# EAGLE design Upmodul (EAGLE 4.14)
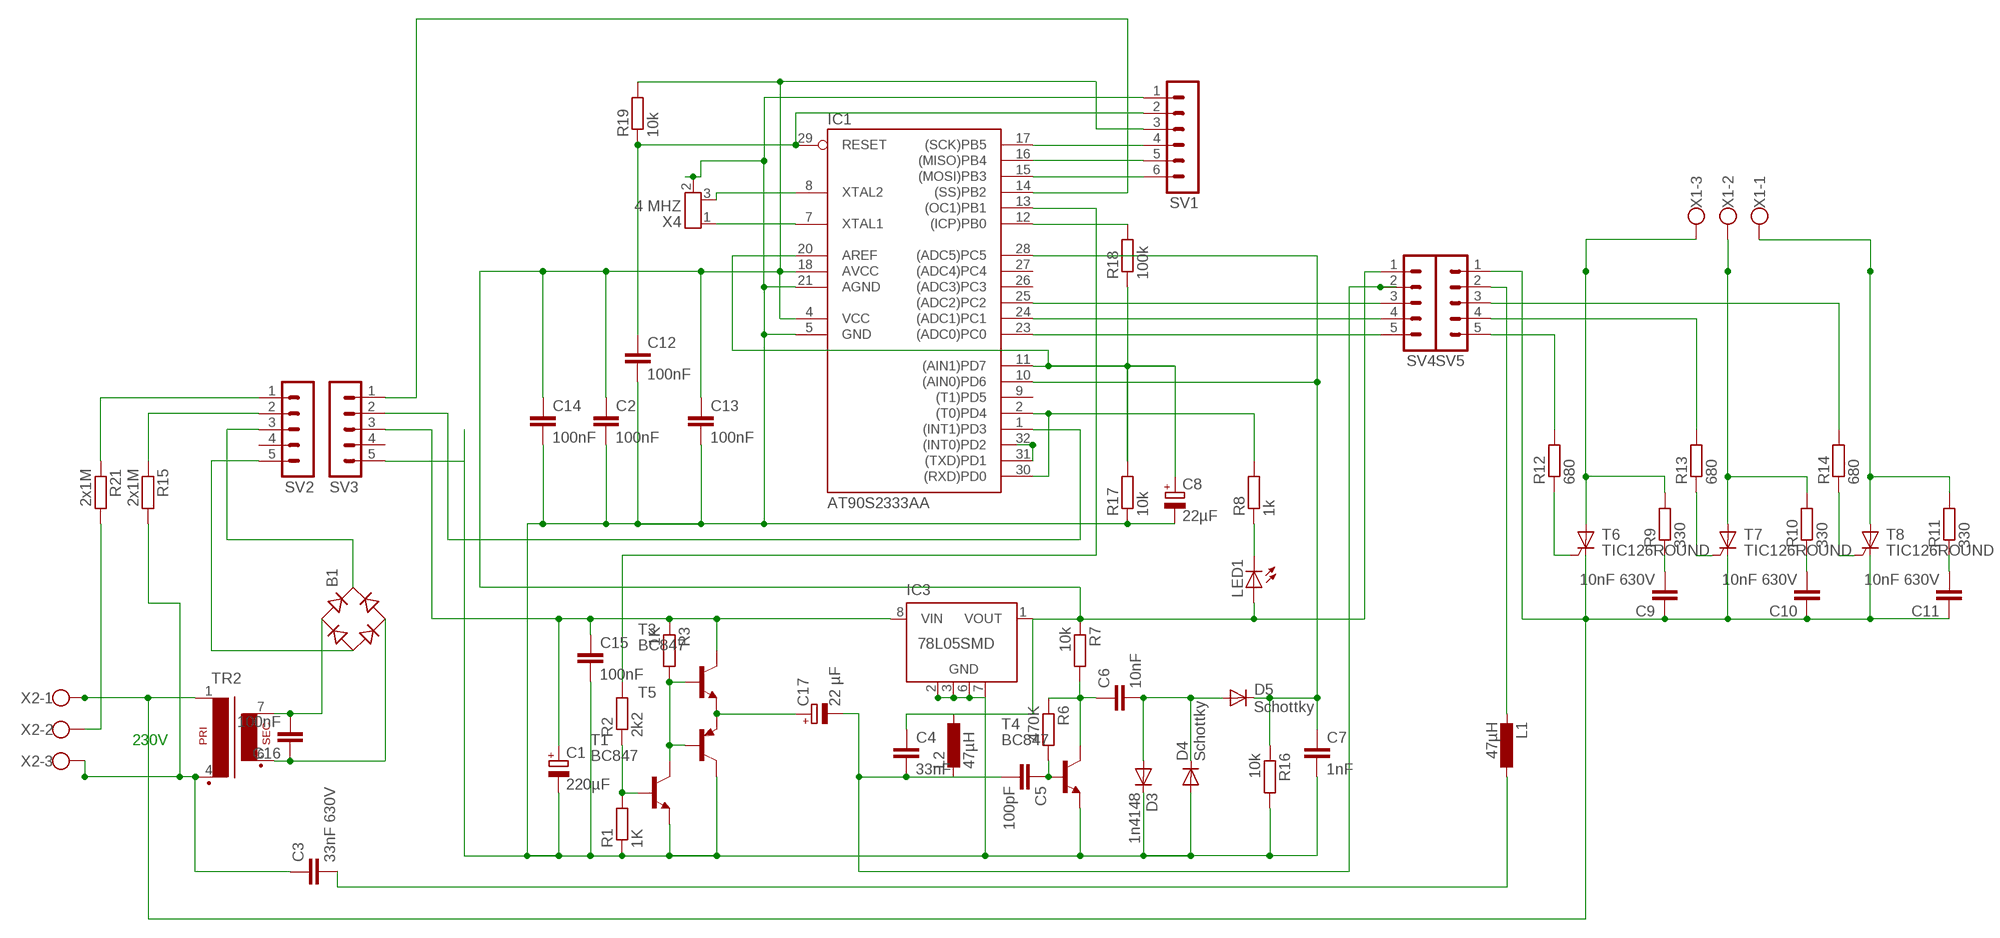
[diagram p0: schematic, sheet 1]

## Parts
B1  B-DIL  [B-DIL]
C1  220µF  CPOL-EUE5-10.5  [E5-10,5]
C2  100nF  C-EUC0805  [C0805]
C3  33nF 630V  C-EU075-032X103  [C075-032X103]
C4  33nF  C-EUC0805  [C0805]
C5  100pF  C-EUC0805  [C0805]
C6  10nF  C-EUC0805  [C0805]
C7  1nF  C-EUC0805  [C0805]
C8  22µF  CPOL-EUE2.5-5  [E2,5-5]
C9  10nF 630V  C-EU075-032X103  [C075-032X103]
C10  10nF 630V  C-EU075-032X103  [C075-032X103]
C11  10nF 630V  C-EU075-032X103  [C075-032X103]
C12  100nF  C-EUC0805  [C0805]
C13  100nF  C-EUC0805  [C0805]
C14  100nF  C-EUC0805  [C0805]
C15  100nF  C-EUC0805  [C0805]
C16  100nF  C-EUC0805  [C0805]
C17  22 µF  CPOL-EUE5-8.5  [E5-8,5]
D3  1n4148  DIODE-DO214AA  [DO214AA]
D4  Schottky  DIODE-DO214AA  [DO214AA]
D5  Schottky  DIODE-DO214AA  [DO214AA]
IC1  AT90S2333AA  [TQFP32-08]
IC3  78L05SMD  [SO08]
L1  47µH  L-EU0207/2V  [0207/2V]
L2  47µH  L-EU0207/2V  [0207/2V]
LED1  LED3MM  [LED3MM]
R1  1K  R-EU_R0805  [R0805]
R2  2k2  R-EU_R0805  [R0805]
R3  1K  R-EU_M0805  [M0805]
R6  470K  R-EU_R0805  [R0805]
R7  10k  R-EU_M0805  [M0805]
R8  1k  R-EU_R0805  [R0805]
R9  330  R-EU_0207/2V  [0207/2V]
R10  330  R-EU_0207/2V  [0207/2V]
R11  330  R-EU_0207/2V  [0207/2V]
R12  680  R-EU_R0805  [R0805]
R13  680  R-EU_R0805  [R0805]
R14  680  R-EU_R0805  [R0805]
R15  2x1M  R-EU_0207/7  [0207/7]
R16  10k  R-EU_M0805  [M0805]
R17  10k  R-EU_R0805  [R0805]
R18  100k  R-EU_R0805  [R0805]
R19  10k  R-EU_R0805  [R0805]
R21  2x1M  R-EU_0207/2V  [0207/2V]
SV1  MA06-1  [MA06-1]
SV2  MA05-1  [MA05-1]
SV3  MA05-1  [MA05-1]
SV4  MA05-1  [MA05-1]
SV5  MA05-1  [MA05-1]
T1  BC847  [SOT23]
T3  BC847  [SOT23]
T4  BC847  [SOT23]
T5  BC857C-PNP-SOT23-BEC  [SOT23-BEC]
T6  TIC126ROUND  [TO220CS-ROUND]
T7  TIC126ROUND  [TO220CS-ROUND]
T8  TIC126ROUND  [TO220CS-ROUND]
TR2  EE20-1ALTERNATIV  [EE20-1-2PIN]
X1  W237-103  [W237-103]
X2  W237-103  [W237-103]
X4  4 MHZ  RESONZTT  [RESONZTT]

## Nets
5V: C2.1 C4.1 C13.1 C14.1 IC1.4(VCC) IC1.18(AVCC) IC3.1(VOUT) L2.1 LED1.A R7.1 R19.2 SV1.3 SV4.1
GND: C1.- C2.2 C7.2 C8.- C12.2 C13.2 C14.2 C15.2 D3.C D4.A IC1.5(GND) IC1.21(AGND) IC3.2(GND) IC3.3(GND) IC3.6(GND) IC3.7(GND) R1.1 R16.2 R17.1 SV1.1 SV3.5 T1.2(E) T4.2(E) T5.C X4.2(GND)
N$1: R1.2 R2.1 T1.1(B)
N$2: C7.1 D5.C IC1.10((AIN0)PD6) IC1.28((ADC5)PC5) R16.1
N$3: C6.1 R6.1 R7.2 T4.3(C)
N$4: C6.2 D3.A D4.C D5.A
N$5: IC1.14((SS)PB2) SV3.1
N$6: C5.1 R6.2 T4.1(B)
N$7: IC1.31((TXD)PD1) IC1.32((INT0)PD2)
N$8: IC1.1((INT1)PD3) SV3.2
N$9: C3.1 R15.2 TR2.4 X2.3
N$10: IC1.15((MOSI)PB3) SV1.6
N$11: C12.1 IC1.29(RESET) R19.1 SV1.2
N$12: LED1.K(C) R8.1
N$14: C1.+ C15.1 IC3.8(VIN) R3.1 SV3.3 T3.3(C)
N$15: R3.2 T1.3(C) T3.1(B) T5.B
N$16: IC1.16((MISO)PB4) SV1.5
N$17: IC1.17((SCK)PB5) SV1.4
N$18: C9.2 R9.1
N$19: B1.AC2 C16.1 TR2.6
N$20: B1.AC1 C16.2 TR2.7
N$21: C10.2 R10.1
N$22: C11.2 R11.1
N$23: R12.2 SV5.5
N$24: R9.2 T6.A X1.3
N$25: R10.2 T7.A X1.2
N$26: R11.2 T8.A X1.1
N$27: R12.1 T6.G
N$28: R13.1 T7.G
N$29: R14.1 T8.G
N$30: IC1.23((ADC0)PC0) SV4.5
N$31: IC1.24((ADC1)PC1) SV4.4
N$32: R14.2 SV5.3
N$33: C4.2 C5.2 C17.- L2.2 SV4.2
N$34: IC1.2((T0)PD4) IC1.30((RXD)PD0) R8.2
N$35: C8.+ IC1.11((AIN1)PD7) IC1.20(AREF) R17.2 R18.1
N$36: IC1.12((ICP)PB0) R18.2
N$37: C17.+ T3.2(E) T5.E
N$38: R13.2 SV5.4
N$39: R21.2 X2.2
N$40: IC1.13((OC1)PB1) R2.2
N$41: IC1.25((ADC2)PC2) SV4.3
N$42: C9.1 C10.1 C11.1 SV5.1 T6.C T7.C T8.C TR2.1 X2.1
N$43: R21.1 SV2.1
N$44: R15.1 SV2.2
N$46: B1.+ SV2.3
N$47: B1.- SV2.5
N$48: C3.2 L1.1
N$49: L1.2 SV5.2
N$52: IC1.7(XTAL1) X4.1(X1)
N$53: IC1.8(XTAL2) X4.3(X2)
Unconnected: IC1.3(NC1) IC1.6(NC2) IC1.9((T1)PD5) IC1.19(NC3) IC1.22(NC4) IC1.26((ADC3)PC3) IC1.27((ADC4)PC4) IC3.4(NC) IC3.5(NC) SV2.4 SV3.4

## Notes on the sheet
- 230V

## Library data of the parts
B1 = rectifier:B-DIL: RECTIFIER
C1 C8 C17 = rcl:CPOL-EU: POLARIZED CAPACITOR, European symbol
C2-C7 C9-C16 = rcl:C-EU: CAPACITOR, European symbol
D3-D5 = diode:DIODE-: DIODE
IC1 = atmel:AT90S2333A: MICROCONTROLLER 2 Kbytes FLASH 128 bytes SRAM 128 bytes EEPROM UART 6-channel 10-bit ADC
IC3 = linear:78L*SMD: Positive VOLTAGE REGULATOR
L1 L2 = rcl:L-EU: INDUCTOR, European symbol
LED1 = led:LED: LED
R1-R3 R6-R19 R21 = rcl:R-EU_: RESISTOR, European symbol
SV1 = con-lstb:MA06-1: PIN HEADER
SV2-SV5 = con-lstb:MA05-1: PIN HEADER
T1 T3 T4 = transistor:BC847: NPN TRANSISTOR
T5 = transistor:*-PNP-: PNP Transistror
T6-T8 = triac:TIC126: THYRISTOR
TR2 = trafo:EE20-1: TRANSFORMER 1 primary winding, 1 secondary winding ERA
X1 X2 = con-wago-500:W237-103: WAGO SCREW CLAMP
X4 = ADS:RESONZTT

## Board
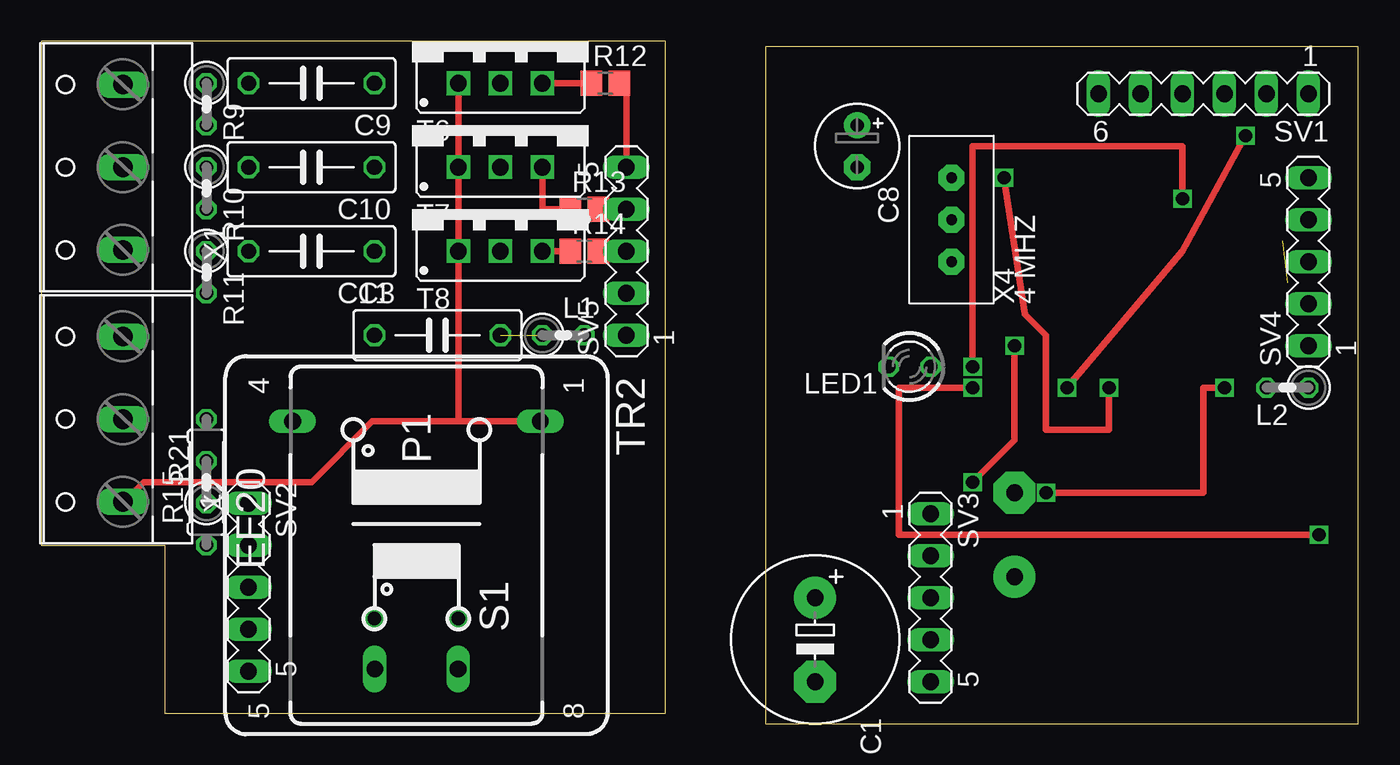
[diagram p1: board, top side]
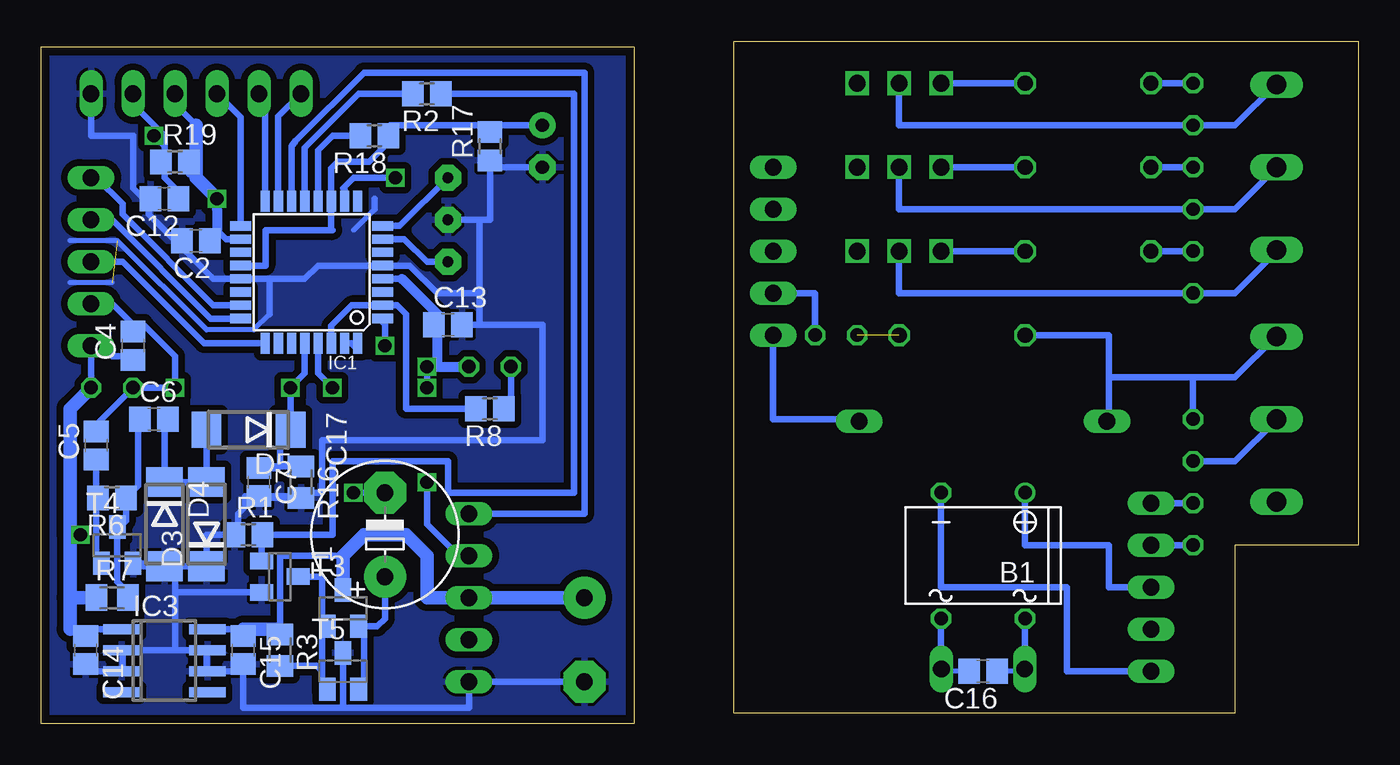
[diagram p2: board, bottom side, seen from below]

Size 79.68 x 41.27 mm. Coordinates in mm from the lower left corner, seen from the top.
Outline: 10.16,0.63 7.94,0.64 7.46,0.63 7.46,10.79 0,10.79 0,41.27 37.77,41.27 37.77,0.64 10.16,0.63
Outline: 9.99,0.63 10.16,0.63
Outline: 43.81,40.95 43.81,0 79.68,0 79.68,40.95 43.81,40.95
Copper layers (1*16): Top 0.035mm / dielectric 1.5mm / Bottom 0.035mm
Design rules "PCB-POOL": minimum track width 6mil, minimum drill 12mil, track to track 6mil, track to pad 6mil, pad to pad 6mil, via to via 6mil, smd to smd 6mil, copper to edge 20mil, drill to drill 8mil, minimum pad ring 8mil, minimum via ring 6mil, stop-mask expansion 3mil, vias tented up to drill 0mil, thermal gap 8mil

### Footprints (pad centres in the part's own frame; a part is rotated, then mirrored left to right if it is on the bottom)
B-DIL = drill 0.813 round: + -2.54,-3.81 | drill 0.813 octagon: - 2.54,-3.81; AC1 2.54,3.81; AC2 -2.54,3.81
E5-10,5 = drill 1.016 pad 2.54 round: + -2.54,0 | drill 1.016 pad 2.54 octagon: - 2.54,0
C0805 = smd 1.3 x 1.5: 1 -0.85,0; 2 0.85,0
C075-032X103 = drill 0.914 octagon: 1 -3.81,0; 2 3.81,0
E2,5-5 = drill 0.813 pad 1.6 round: + -1.27,0 | drill 0.813 pad 1.6 octagon: - 1.27,0
E5-8,5 = drill 1.016 pad 2.54 round: + -2.54,0 | drill 1.016 pad 2.54 octagon: - 2.54,0
DO214AA = smd 1.8 x 2.2: A 2.55,0; C -2.55,0
TQFP32-08 = smd 1.27 x 0.559: 1 -4.293,2.8; 2 -4.293,2; 3 -4.293,1.2; 4 -4.293,0.4; 5 -4.293,-0.4; 6 -4.293,-1.2; 7 -4.293,-2; 8 -4.293,-2.8; 17 4.293,-2.8; 18 4.293,-2; 19 4.293,-1.2; 20 4.293,-0.4; 21 4.293,0.4; 22 4.293,1.2; 23 4.293,2; 24 4.293,2.8 | smd 0.559 x 1.27: 9 -2.8,-4.293; 10 -2,-4.293; 11 -1.2,-4.293; 12 -0.4,-4.293; 13 0.4,-4.293; 14 1.2,-4.293; 15 2,-4.293; 16 2.8,-4.293; 25 2.8,4.293; 26 2,4.293; 27 1.2,4.293; 28 0.4,4.293; 29 -0.4,4.293; 30 -1.2,4.293; 31 -2,4.293; 32 -2.8,4.293
SO08 = smd 0.6 x 2.2: 1 -1.905,-2.6; 2 -0.635,-2.6; 3 0.635,-2.6; 4 1.905,-2.6; 5 1.905,2.6; 6 0.635,2.6; 7 -0.635,2.6; 8 -1.905,2.6
0207/2V = drill 0.813 octagon: 1 -1.27,0; 2 1.27,0
LED3MM = drill 0.813 octagon: A -1.27,0; K 1.27,0
R0805 = smd 1.3 x 1.5: 1 -0.85,0; 2 0.85,0
M0805 = smd 1.3 x 1.6: 1 -0.95,0; 2 0.95,0
0207/7 = drill 0.813 octagon: 1 -3.81,0; 2 3.81,0
MA06-1 = drill 1.016 long: 1 -6.35,0; 2 -3.81,0; 3 -1.27,0; 4 1.27,0; 5 3.81,0; 6 6.35,0
MA05-1 = drill 1.016 long: 1 -5.08,0; 2 -2.54,0; 3 0,0; 4 2.54,0; 5 5.08,0
SOT23 = smd 1 x 1.4: 1 -0.95,-1.1; 2 0.95,-1.1; 3 0,1.1
SOT23-BEC = smd 1 x 1.4: B -0.95,-1.1; C 0,1.1; E 0.95,-1.1
TO220CS-ROUND = drill 1.016 square: A 0,-2.54; C -2.54,-2.54; G 2.54,-2.54
EE20-1-2PIN = drill 1.016 long: 1 -7.493,7.493; 4 -7.493,-7.493; 6 7.493,-2.515; 7 7.493,2.515
W237-103 = drill 1.194 long: 1 -5,-1.29; 2 0,-1.29; 3 5,-1.29
RESONZTT = drill 0.66 pad 1.575 octagon: 1 0,0; 2 2.54,0; 3 5.08,0

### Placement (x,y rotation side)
B1  22.7,10.16 180 bottom
C1  46.83,5.08 270 top
C2  70.32,29.21 180 bottom
C3  23.96,23.49 0 top
C4  74.13,22.86 90 bottom
C5  76.35,16.82 90 bottom
C6  72.86,18.41 0 bottom
C7  66.51,14.6 270 bottom
C8  49.37,34.92 270 top
C9  16.34,38.73 180 top
C10  16.34,33.65 180 top
C11  16.34,28.57 180 top
C12  72.23,31.74 180 bottom
C13  55.08,24.12 0 bottom
C14  76.99,4.44 270 bottom
C15  67.46,4.44 270 bottom
C16  22.7,3.17 180 bottom
C17  58.89,11.43 90 bottom
D3  69.69,12.06 90 bottom
D4  72.23,12.06 270 bottom
D5  67.15,17.78 180 bottom
IC1  63.34,27.3 180 bottom
IC3  72.23,3.8 270 bottom
L1  31.59,23.49 0 top
L2  75.4,20.32 180 top
LED1  52.54,21.59 180 top
R1  67.15,11.43 0 bottom
R2  56.35,38.1 180 bottom
R3  65.24,4.44 270 bottom
R6  75.4,13.65 180 bottom
R7  75.4,7.62 0 bottom
R8  52.54,19.05 180 bottom
R9  9.99,37.46 270 top
R10  9.99,32.38 270 top
R11  9.99,27.3 270 top
R12  34.12,38.73 0 top
R13  32.85,31.11 0 top
R14  32.85,28.57 0 top
R15  9.99,14.6 90 top
R16  63.97,14.6 270 bottom
R17  52.54,34.92 90 bottom
R18  59.52,35.55 180 bottom
R19  71.59,33.97 0 bottom
R21  9.99,14.6 90 top
SV1  70.32,38.1 180 top
SV2  12.54,8.25 270 top
SV3  53.81,7.62 270 top
SV4  76.67,27.94 90 top
SV5  35.4,28.57 90 top
T1  65.24,8.89 270 bottom
T3  61.43,6.98 0 bottom
T4  75.08,10.79 0 bottom
T5  61.43,3.17 0 bottom
T6  27.77,41.27 0 top
T7  27.77,36.19 0 top
T8  27.77,31.11 0 top
TR2  22.7,10.79 270 top
X1  3.65,33.65 90 top
X2  3.65,18.41 90 top
X4  55.08,27.94 90 top

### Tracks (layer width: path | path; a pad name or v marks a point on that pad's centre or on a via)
5V  (via drill 0.8)
  Top 0.406: v69.05,31.74 69.05,34.92 56.35,34.92 v56.35,21.59 | v77.31,11.43 51.91,11.43 51.91,20.32 v56.35,20.32
  Bottom 0.406: 70.32,36.19 71.59,37.46 SV1.3 | R19.2 70.74,33.23 70.32,33.65 | C14.1 77.94,5.71 IC3.1 | 57.85,26.9 IC1.4 | C13.1 55.71,24.12 55.71,24.76 | LED1.A 55.71,21.59 | IC1.18 68.51,29.3 69.05,29.84 69.47,29.42 C2.1 | v77.31,11.43 77.94,11.43 | v56.35,20.32 v56.35,21.59 | L2.1 SV4.1 76.04,22.86 75.4,22.22 74.13,22.22 C4.1 | v69.05,31.74 69.05,31.11
  Bottom 0.61: 55.71,24.76 57.85,26.9 | 55.71,21.59 55.71,24.12 | 69.05,31.11 69.05,29.84 | v56.35,21.59 LED1.A
  Bottom 0.813: 70.32,36.19 70.32,33.65 70.32,33.02 v69.05,31.74 | 77.94,7.62 77.94,5.71 | 77.94,7.62 77.94,11.43 77.94,19.05 L2.1 | 77.94,7.62 R7.1
GND  (1 unrouted)
  Bottom 0.305: 77.94,29.21 75.08,29.21 69.69,23.81 66.83,23.81 65.88,24.76 | 60.8,29.84 59.52,31.11 | 75.4,26.66 77.94,26.66
  Bottom 0.406: SV1.1 76.67,35.55 74.13,35.55 74.13,32.38 73.18,31.43 73.18,30.79 | 65.88,26.9 63.74,26.9 62.93,27.7 IC1.5 57.38,27.7 55.71,26.03 53.17,26.03 | 65.88,26.9 IC1.21 69.29,26.9 73.18,30.79 | 53.17,26.03 53.17,30.48 | 61.43,0.95 53.81,0.95 SV3.5 C1.- 46.83,1.9 | 67.15,3.8 C15.2 67.46,3.17 | 61.43,0.95 67.46,0.95 67.46,3.17 | 67.46,3.17 IC3.6 69.69,3.17 69.69,4.44 | 69.69,4.44 IC3.7 | 69.69,4.44 71.59,4.44 | 71.59,4.44 74.77,4.44 | 74.77,4.44 IC3.2 | 74.77,4.44 74.77,3.17 IC3.3 76.67,3.17 C14.2 | 71.59,4.44 71.59,7.93 | 71.59,7.93 71.59,9.52 | 71.59,9.52 73.67,9.69 T4.2 73.96,9.69 74.13,9.52 74.12,9.51 D4.A 71.59,9.52 | 61.43,0.95 T5.C | T1.2 71.59,7.94 71.59,7.93 | 71.59,9.52 71.58,9.51 D3.C 69.69,11.43 R1.1 67.78,11.43 67.78,12.7 67.36,13.12 67.36,13.75 | 67.36,13.75 C7.2 66.51,13.65 67.14,13.65 R16.2 | 49.37,24.12 C13.2 | 49.37,24.12 53.17,24.12 53.17,26.03 | 67.36,13.75 64.19,13.75 63.97,13.97 62.7,13.97 62.7,17.14 49.37,17.14 49.37,24.12 | 53.17,30.48 X4.2 | C8.- 52.54,33.65 R17.1 52.54,30.48 53.17,30.48 | 65.88,26.9 65.88,24.76 | 59.52,31.11 59.52,31.74 | 73.18,30.79 C12.2
  pour Bottom (isolate 0.406): 44.28,0.63 44.28,40.63 79.21,40.63 79.21,0.63
N$1
  Bottom 0.406: T1.1 66.34,11.28 66.19,11.43 R1.2 62.07,11.43 62.07,15.87 55.08,15.87 55.08,13.97 47.46,13.97 47.46,38.1 R2.1
N$2  (via drill 0.8)
  Top 0.406: v58.26,33.02 59.52,24.76 60.8,23.49 60.8,17.78 D5.C v64.61,20.32
  Bottom 0.406: 65.56,15.55 R16.1 65.24,15.55 | C7.1 65.34,15.45 65.24,15.55 | 65.24,17.78 65.24,15.55 | IC1.10 61.34,32.29 61.43,32.38 60.8,33.02 v58.26,33.02 | 65.24,17.78 D5.C | 65.24,17.78 D5.C v64.61,20.32 63.74,21.19 IC1.28
N$3
  Bottom 0.406: R7.2 74.13,7.62 75.08,8.57 T4.3 74.94,11.89 74.55,12.28 R6.1 73.81,14.39 73.81,18.41 C6.1
N$4
  Bottom 0.406: C6.2 72.23,17.78 D4.C 71.59,14.6 D4.C D3.A | D3.A 69.05,14.6 69.06,14.61 D3.A | D5.A 69.69,17.78 D3.A
N$5
  Bottom 0.406: IC1.14 64.54,34.92 64.29,35.24 60.16,39.37 46.83,39.37 46.83,12.7 SV3.1
N$6
  Bottom 0.406: 76.25,13.55 76.04,13.33 | 76.25,13.55 R6.2 76.25,13.75 | 76.35,13.65 C5.1 | 76.35,13.65 76.25,13.55 | T4.1 76.03,9.84 76.35,10.16 76.35,13.65 | 76.25,13.75 76.04,13.97 | 76.35,13.65 76.25,13.75
N$7
  Bottom 0.406: IC1.32 60.64,23.01 60.8,22.86 60.95,23.01 IC1.31
N$8  (via drill 0.8)
  Top 0.406: v58.89,22.86 58.89,17.14 v56.35,14.6
  Bottom 0.406: SV3.2 54.45,10.16 56.35,12.06 v56.35,14.6 | IC1.1 59.04,24.28 58.89,24.12 v58.89,22.86
N$9
  Bottom 0.406: X2.3 5,23.41 7.46,20.95 9.99,20.95 | 9.99,20.95 15.07,20.95 | TR2.4 15.07,18.41 15.07,20.95 | 9.99,20.95 R15.2 | 15.07,20.95 15.07,23.49 C3.1
N$10
  Bottom 0.406: IC1.15 65.34,36.73 SV1.6
N$11  (via drill 0.8)
  Top 0.406: v72.86,35.55 69.05,28.57 v62.07,20.32
  Bottom 0.406: SV1.2 74.13,37.46 72.23,35.55 72.23,34.92 | 72.23,33.65 R19.1 72.44,33.44 72.23,33.65 | 72.23,34.92 72.23,33.65 | IC1.29 62.93,21.19 v62.07,20.32 | C12.1 71.38,32.16 72.23,33.02 72.23,33.65 | v72.86,35.55 72.23,34.92
N$12
  Bottom 0.406: R8.1 51.27,19.05 LED1.K
N$14
  Bottom 0.406: C15.1 67.46,5.71 IC3.8 | 65.24,5.71 R3.1 | 61.43,10.16 65.24,10.16 65.24,5.71 | 65.24,5.71 65.24,5.08
  Bottom 0.813: C1.+ SV3.3 56.35,7.62 56.35,10.16 57.62,11.43 60.16,11.43 61.43,10.16 T3.3 | 65.24,5.71 67.46,5.71
N$15
  Bottom 0.406: T5.B 62.53,2.07 62.7,1.9 62.7,3.17 | 62.7,3.17 62.7,5.71 | R3.2 63.02,3.49 62.7,3.17 | T1.3 62.7,8.89 62.7,5.71 | 62.7,5.71 62.53,5.88 T3.1
N$16
  Bottom 0.406: IC1.16 66.14,37.09 66.51,37.46 SV1.5
N$17
  Bottom 0.406: IC1.17 67.63,36.67 SV1.4
N$18
  Bottom 0.406: R9.1 C9.2
N$19
  Bottom 0.305: TR2.6 20.18,3.17 20.16,3.17 C16.1
  Bottom 0.406: TR2.6 20.18,3.2 20.16,3.17 B1.AC2
N$20
  Bottom 0.305: TR2.7 25.21,3.17 25.23,3.17 C16.2
  Bottom 0.406: TR2.7 25.21,3.2 25.23,3.17 B1.AC1
N$21
  Bottom 0.406: R10.1 C10.2
N$22
  Bottom 0.406: R11.1 C11.2
N$23
  Top 0.406: R12.2 35.4,38.73 SV5.5
N$24
  Bottom 0.406: 4.94,38.71 4.92,38.73 | X1.3 4.94,38.71 | 4.94,38.71 7.46,36.19 R9.2 27.77,36.19 T6.A
N$25
  Bottom 0.406: X1.2 4.92,33.65 7.46,31.11 R10.2 27.77,31.11 T7.A
N$26
  Bottom 0.406: X1.1 4.94,28.59 4.92,28.57 7.46,26.03 R11.2 27.77,26.03 T8.A
N$27
  Top 0.406: T6.G R12.1
N$28
  Top 0.406: R13.1 30.31,31.11 T7.G
N$29
  Top 0.406: T8.G R14.1
N$30
  Bottom 0.406: IC1.23 69.27,25.3 74.77,30.79 74.77,31.43 76.35,33.02 SV4.5
N$31
  Bottom 0.406: IC1.24 69.43,24.5 75.4,30.48 SV4.4
N$32
  Top 0.406: SV5.3 R14.2
N$33  (via drill 0.8)
  Top 0.406: v60.8,13.97 70.32,13.97 70.32,20.32 v71.59,20.32
  Bottom 0.406: C17.- v60.8,13.97 | C5.2 76.57,17.67 76.67,17.78 L2.2 v71.59,20.32 71.59,22.22 73.39,24.02 C4.2 74.13,24.12 75.4,25.4 SV4.2
N$34
  Bottom 0.406: IC1.30 62.13,24.05 60.89,25.3 IC1.2 58.16,25.3 57.62,24.76 57.62,19.05 R8.2 55.08,19.05
N$35
  Bottom 0.406: IC1.20 66.11,27.7 66.11,29.84 62.13,29.84 | C8.+ 52.54,36.19 | 52.54,36.19 R17.2 | 52.54,36.19 58.57,36.19 R18.1 58.89,35.55 58.57,35.24 59.84,33.97 61.75,33.97 62.13,33.58 IC1.11 62.13,29.84 | 62.13,29.84 62.07,29.84
N$36
  Bottom 0.406: R18.2 62.07,35.55 62.93,34.69 IC1.12
N$37
  Bottom 0.406: T5.E 60.48,2.22 60.16,2.54 60.16,5.71 60.33,5.88 | 60.33,5.88 T3.2 | 60.33,5.88 59.35,5.88 58.89,6.35 C17.+
N$38
  Top 0.406: SV5.4 R13.2
N$39
  Bottom 0.406: X2.2 4.94,18.39 7.46,15.87 R21.2
N$40
  Bottom 0.406: IC1.13 63.74,34.84 60.48,38.1 60.16,38.1 R2.2
N$41
  Bottom 0.406: IC1.25 69.84,23.01 74.77,27.94 SV4.3
N$42
  Top 0.406: 25.23,18.28 TR2.1 | T6.C T7.C T8.C 25.23,18.28 | 25.23,18.28 20.03,18.28 16.34,14.6 6.19,14.6 4.94,13.35 | 4.94,13.35 4.92,13.33 | X2.1 4.94,13.35
  Bottom 0.406: T8.C C11.1 | T7.C C10.1 | T6.C C9.1 | SV5.1 35.4,18.41 30.95,18.41 30.31,17.78 30.31,18.41 TR2.1
N$43
  Bottom 0.406: R21.1 SV2.1
N$44
  Bottom 0.406: R15.1 SV2.2
N$46
  Bottom 0.406: B1.+ 20.16,10.79 15.07,10.79 15.07,8.25 SV2.3
N$47
  Bottom 0.406: B1.- 25.23,8.25 17.61,8.25 17.61,3.17 SV2.5
N$48  (1 unrouted)
N$49
  Bottom 0.406: L1.2 32.85,26.03 SV5.2
N$52
  Bottom 0.406: IC1.7 57.71,29.3 56.35,27.94 X4.1
N$53
  Bottom 0.406: IC1.8 57.99,30.1 X4.3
